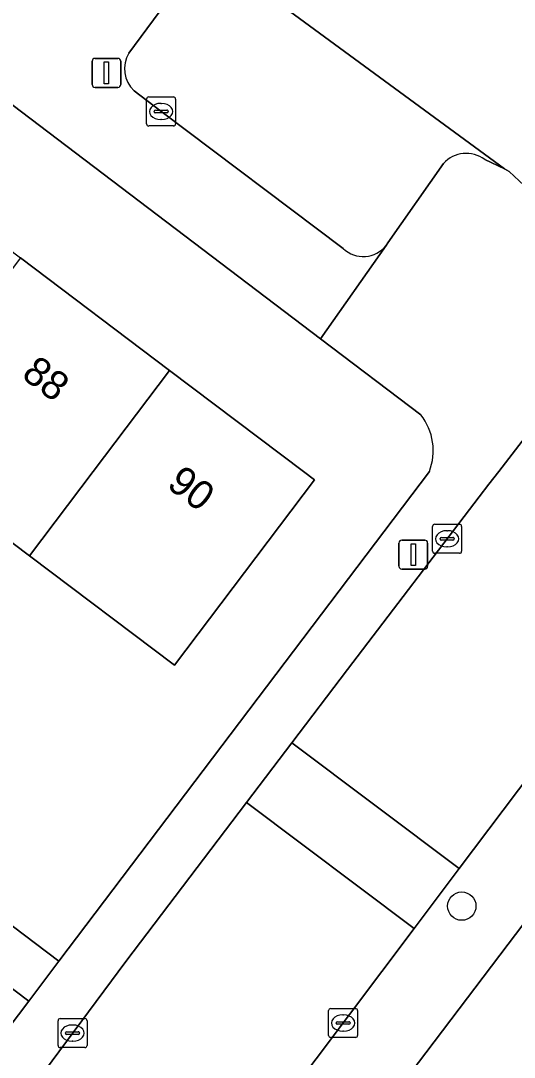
# Model space of a CAD drawing. Extents: x 159039 to 160102, y 381214 to 382524.
# Drawn here: x 159397.3 to 159414.31, y 381979.8 to 382015.54 of the extents above; entities that cross this region are included whole.
import ezdxf

# ---------------------------------------------------------------- set-up
doc = ezdxf.new("R2010")
doc.units = 0
for name, color, linetype in [('IMGEO_Boom', 7, 'Continuous'), ('IMGEO_Erf', 7, 'Continuous'), ('IMGEO_Kolk', 7, 'Continuous'), ('IMGEO_Lichtmast', 7, 'Continuous'), ('IMGEO_Pand', 7, 'Continuous'), ('IMGEO_Pand_nummerreeks', 7, 'Continuous'), ('IMGEO_Parkeervlak_open', 7, 'Continuous'), ('IMGEO_Rijbaan_lokaal_open', 7, 'Continuous'), ('IMGEO_Voetpad_open', 7, 'Continuous')]:
    doc.layers.add(name, color=color, linetype=linetype)

msp = doc.modelspace()

# ---------------------------------------------------------------- linework, layer by layer
at = {"layer": 'IMGEO_Boom'}
msp.add_circle((159412.501, 381985.013), 0.489, dxfattribs=at)
at = {"layer": 'IMGEO_Erf'}
for points in [[(159411.089, 382001.953), (159407.637, 382004.575), (159384.813, 382021.909), (159383.652, 382020.387), (159382.339, 382018.664), (159387.453, 382014.8), (159392.433, 382011.038), (159397.288, 382007.369), (159402.43, 382003.484), (159407.041, 382000), (159407.427, 381999.708), (159402.603, 381993.319), (159397.601, 381997.092), (159393.746, 382000), (159392.457, 382000.974), (159387.601, 382004.643)], [(159387.601, 382004.643), (159382.622, 382008.405), (159377.507, 382012.27), (159372.531, 382005.718), (159377.753, 382001.769), (159376.399, 381999.977), (159378.033, 381998.727), (159379.808, 382001.045), (159383.023, 381998.584), (159386.025, 381996.287), (159384.251, 381993.969), (159388.033, 381991.176), (159389.808, 381993.494), (159393.023, 381991.033), (159396.025, 381988.736), (159394.251, 381986.418), (159398.618, 381983.116), (159411.384, 382000)], [(159421.683, 381993.713), (159398.906, 381963.628), (159402.187, 381961.144), (159405.915, 381966.068), (159409.669, 381971.027), (159413.342, 381975.878), (159417.049, 381980.775), (159420.747, 381985.661), (159424.404, 381990.491), (159430.843, 381985.616), (159427.826, 381981.63), (159427.186, 381980.785), (159429.997, 381978.658), (159426.299, 381973.772), (159423.488, 381975.899), (159419.78, 381971.003), (159422.368, 381969.043), (159420.853, 381967.042), (159418.265, 381969.001), (159416.107, 381966.151), (159412.354, 381961.193), (159408.626, 381956.269), (159416.944, 381949.973)], [(159383.263, 381962.809), (159397.577, 381981.74), (159393.23, 381985.027)]]:
    msp.add_lwpolyline(points, dxfattribs=at)
msp.add_arc((159409.522, 382000.718), 1.996, 338.9276, 38.2515, dxfattribs=at)
at = {"layer": 'IMGEO_Kolk'}
for p, q in [((159401.638, 382011.988), (159401.638, 382012.84)), ((159401.713, 382012.914), (159402.565, 382012.914)), ((159402.126, 382012.694), (159402.151, 382012.694)), ((159402.639, 382012.84), (159402.639, 382011.988)), ((159401.897, 382012.408), (159401.897, 382012.42)), ((159402.335, 382012.371), (159401.937, 382012.371)), ((159401.94, 382012.457), (159402.338, 382012.457)), ((159402.381, 382012.42), (159402.381, 382012.408)), ((159402.565, 382011.914), (159401.713, 382011.914)), ((159402.149, 382012.134), (159402.124, 382012.134)), ((159411.495, 381997.253), (159411.495, 381998.105)), ((159411.57, 381998.179), (159412.422, 381998.179)), ((159411.983, 381997.959), (159412.008, 381997.959)), ((159412.496, 381998.105), (159412.496, 381997.253)), ((159411.754, 381997.673), (159411.754, 381997.685)), ((159412.192, 381997.636), (159411.794, 381997.636)), ((159411.797, 381997.722), (159412.195, 381997.722)), ((159412.238, 381997.685), (159412.238, 381997.673)), ((159412.006, 381997.399), (159411.981, 381997.399)), ((159412.422, 381997.179), (159411.57, 381997.179)), ((159407.911, 381980.557), (159407.911, 381981.409)), ((159407.986, 381981.483), (159408.838, 381981.483)), ((159408.399, 381981.263), (159408.424, 381981.263)), ((159408.912, 381981.409), (159408.912, 381980.557)), ((159398.585, 381980.208), (159398.585, 381981.06)), ((159398.66, 381981.134), (159399.512, 381981.134)), ((159399.073, 381980.914), (159399.098, 381980.914)), ((159399.586, 381981.06), (159399.586, 381980.208)), ((159408.17, 381980.977), (159408.17, 381980.989)), ((159408.608, 381980.94), (159408.21, 381980.94)), ((159408.213, 381981.026), (159408.611, 381981.026)), ((159408.654, 381980.989), (159408.654, 381980.977)), ((159398.844, 381980.628), (159398.844, 381980.64)), ((159399.282, 381980.591), (159398.884, 381980.591)), ((159398.887, 381980.677), (159399.285, 381980.677)), ((159399.328, 381980.64), (159399.328, 381980.628)), ((159408.838, 381980.483), (159407.986, 381980.483)), ((159408.422, 381980.703), (159408.397, 381980.703)), ((159399.512, 381980.134), (159398.66, 381980.134)), ((159399.096, 381980.354), (159399.071, 381980.354))]:
    msp.add_line(p, q, dxfattribs=at)
for points in [[(159401.638, 382011.988), (159401.638, 382012.84)], [(159401.713, 382012.914), (159402.565, 382012.914)], [(159402.639, 382012.84), (159402.639, 382011.988)], [(159402.565, 382011.914), (159401.713, 382011.914)], [(159411.495, 381997.253), (159411.495, 381998.105)], [(159411.57, 381998.179), (159412.422, 381998.179)], [(159412.496, 381998.105), (159412.496, 381997.253)], [(159412.422, 381997.179), (159411.57, 381997.179)], [(159407.911, 381980.557), (159407.911, 381981.409)], [(159407.986, 381981.483), (159408.838, 381981.483)], [(159408.912, 381981.409), (159408.912, 381980.557)], [(159398.585, 381980.208), (159398.585, 381981.06)], [(159398.66, 381981.134), (159399.512, 381981.134)], [(159399.586, 381981.06), (159399.586, 381980.208)], [(159408.838, 381980.483), (159407.986, 381980.483)], [(159399.512, 381980.134), (159398.66, 381980.134)]]:
    msp.add_lwpolyline(points, dxfattribs=at)
for centre, radius, start, end in [((159401.715, 382012.838), 0.0765, 91.552, 178.448), ((159401.715, 382012.838), 0.0765, 91.552, 178.448), ((159402.563, 382012.838), 0.0765, 1.552, 88.448), ((159402.563, 382012.838), 0.0765, 1.552, 88.448), ((159401.937, 382012.417), 0.0403, 85.8775, 175.7526), ((159401.934, 382012.407), 0.0366, 178.938, 274.7102), ((159402.338, 382012.414), 0.043, 264.8664, 352.4533), ((159402.342, 382012.419), 0.0386, 1.7309, 96.639), ((159401.715, 382011.99), 0.0765, 181.552, 268.448), ((159401.715, 382011.99), 0.0765, 181.552, 268.448), ((159402.563, 382011.99), 0.0765, 271.552, 358.448), ((159402.563, 382011.99), 0.0765, 271.552, 358.448), ((159411.572, 381998.103), 0.0765, 91.552, 178.448), ((159411.572, 381998.103), 0.0765, 91.552, 178.448), ((159412.42, 381998.103), 0.0765, 1.552, 88.448), ((159412.42, 381998.103), 0.0765, 1.552, 88.448), ((159411.794, 381997.682), 0.0403, 85.8775, 175.7526), ((159411.791, 381997.672), 0.0366, 178.938, 274.7102), ((159412.195, 381997.679), 0.043, 264.8664, 352.4533), ((159412.199, 381997.684), 0.0386, 1.7309, 96.639), ((159411.572, 381997.255), 0.0765, 181.552, 268.448), ((159411.572, 381997.255), 0.0765, 181.552, 268.448), ((159412.42, 381997.255), 0.0765, 271.552, 358.448), ((159412.42, 381997.255), 0.0765, 271.552, 358.448), ((159407.988, 381981.407), 0.0765, 91.552, 178.448), ((159407.988, 381981.407), 0.0765, 91.552, 178.448), ((159408.836, 381981.407), 0.0765, 1.552, 88.448), ((159408.836, 381981.407), 0.0765, 1.552, 88.448), ((159398.662, 381981.058), 0.0765, 91.552, 178.448), ((159398.662, 381981.058), 0.0765, 91.552, 178.448), ((159399.51, 381981.058), 0.0765, 1.552, 88.448), ((159399.51, 381981.058), 0.0765, 1.552, 88.448), ((159408.21, 381980.986), 0.0403, 85.8775, 175.7526), ((159408.207, 381980.976), 0.0366, 178.938, 274.7102), ((159408.611, 381980.983), 0.043, 264.8664, 352.4533), ((159408.615, 381980.988), 0.0386, 1.7309, 96.639), ((159398.884, 381980.637), 0.0403, 85.8775, 175.7526), ((159398.881, 381980.627), 0.0366, 178.938, 274.7102), ((159399.285, 381980.634), 0.043, 264.8664, 352.4533), ((159399.289, 381980.639), 0.0386, 1.7309, 96.639), ((159407.988, 381980.559), 0.0765, 181.552, 268.448), ((159407.988, 381980.559), 0.0765, 181.552, 268.448), ((159408.836, 381980.559), 0.0765, 271.552, 358.448), ((159408.836, 381980.559), 0.0765, 271.552, 358.448), ((159398.662, 381980.21), 0.0765, 181.552, 268.448), ((159398.662, 381980.21), 0.0765, 181.552, 268.448), ((159399.51, 381980.21), 0.0765, 271.552, 358.448), ((159399.51, 381980.21), 0.0765, 271.552, 358.448)]:
    msp.add_arc(centre, radius, start, end, dxfattribs=at)
for centre, major_axis, ratio, start_param, end_param in [((159402.125, 382012.414), (-0.387, 0.002), 0.722429, 4.712389, 7.853982), ((159402.15, 382012.414), (-0.39, 0.002), 0.717154, 1.570796, 4.712389), ((159411.982, 381997.679), (-0.387, 0.002), 0.722429, 4.712389, 7.853982), ((159412.007, 381997.679), (-0.39, 0.002), 0.717154, 1.570796, 4.712389), ((159408.398, 381980.983), (-0.387, 0.002), 0.722429, 4.712389, 7.853982), ((159408.423, 381980.983), (-0.39, 0.002), 0.717154, 1.570796, 4.712389), ((159399.072, 381980.634), (-0.387, 0.002), 0.722429, 4.712389, 7.853982), ((159399.097, 381980.634), (-0.39, 0.002), 0.717154, 1.570796, 4.712389)]:
    msp.add_ellipse(centre, major_axis=major_axis, ratio=ratio, start_param=start_param, end_param=end_param, dxfattribs=at)
at = {"layer": 'IMGEO_Lichtmast'}
for p, q in [((159399.761, 382013.346), (159399.761, 382014.146)), ((159399.761, 382014.146), (159399.761, 382013.346)), ((159399.861, 382014.246), (159400.651, 382014.246)), ((159400.651, 382014.246), (159399.861, 382014.246)), ((159400.751, 382014.146), (159400.751, 382013.346)), ((159400.751, 382013.346), (159400.751, 382014.146)), ((159400.651, 382013.246), (159399.861, 382013.246)), ((159399.861, 382013.246), (159400.651, 382013.246)), ((159410.433, 381997.634), (159411.223, 381997.634)), ((159411.223, 381997.634), (159410.433, 381997.634)), ((159410.333, 381996.734), (159410.333, 381997.534)), ((159410.333, 381997.534), (159410.333, 381996.734)), ((159411.323, 381997.534), (159411.323, 381996.734)), ((159411.323, 381996.734), (159411.323, 381997.534)), ((159411.223, 381996.634), (159410.433, 381996.634)), ((159410.433, 381996.634), (159411.223, 381996.634))]:
    msp.add_line(p, q, dxfattribs=at)
for points in [[(159400.181, 382014.121), (159400.331, 382014.121), (159400.331, 382013.371), (159400.181, 382013.371), (159400.181, 382014.121)], [(159410.753, 381997.509), (159410.903, 381997.509), (159410.903, 381996.759), (159410.753, 381996.759), (159410.753, 381997.509)]]:
    msp.add_lwpolyline(points, dxfattribs=at)
for centre, start, end in [((159399.861, 382014.146), 90, 180), ((159399.861, 382014.146), 90, 180), ((159400.651, 382014.146), 0, 90), ((159400.651, 382014.146), 360, 90), ((159399.861, 382013.346), 180, 270), ((159399.861, 382013.346), 180, 270), ((159400.651, 382013.346), 270, 0), ((159400.651, 382013.346), 270, 0), ((159410.433, 381997.534), 90, 180), ((159410.433, 381997.534), 90, 180), ((159411.223, 381997.534), 0, 90), ((159411.223, 381997.534), 360, 90), ((159410.433, 381996.734), 180, 270), ((159410.433, 381996.734), 180, 270), ((159411.223, 381996.734), 270, 0), ((159411.223, 381996.734), 270, 0)]:
    msp.add_arc(centre, 0.1, start, end, dxfattribs=at)
at = {"layer": 'IMGEO_Pand'}
for points in [[(159392.457, 382000.974), (159393.746, 382000), (159397.601, 381997.092), (159399.798, 382000), (159402.43, 382003.484), (159397.288, 382007.369)], [(159397.601, 381997.092), (159402.603, 381993.319), (159407.427, 381999.708), (159407.041, 382000), (159402.43, 382003.484), (159399.798, 382000)]]:
    msp.add_lwpolyline(points, close=True, dxfattribs=at)
at = {"layer": 'IMGEO_Parkeervlak_open'}
for points in [[(159413.29, 382010.753), (159413.97, 382010.442), (159403.117, 382018.417)], [(159402.922, 382017.001), (159401.024, 382014.421)], [(159401.208, 382013.131), (159402.125, 382012.426), (159408.415, 382007.686)], [(159409.892, 382007.795), (159409.957, 382007.888), (159411.869, 382010.619)]]:
    msp.add_lwpolyline(points, dxfattribs=at)
for centre, radius, start, end in [((159401.905, 382013.889), 1.03, 148.862, 227.3733), ((159412.653, 382009.91), 1.057, 52.9226, 137.8515), ((159409.104, 382008.416), 1.004, 226.6775, 321.7639)]:
    msp.add_arc(centre, radius, start, end, dxfattribs=at)
at = {"layer": 'IMGEO_Rijbaan_lokaal_open'}
for points in [[(159403.117, 382018.417), (159413.97, 382010.442), (159414.131, 382010.342), (159414.649, 382009.857), (159428.781, 381998.963), (159429.268, 381998.566), (159433.841, 381994.834), (159441.923, 381988.326)], [(159416.185, 382003.138), (159413.774, 382000), (159413.438, 381999.563), (159413.105, 381999.127), (159408.558, 381993.176), (159406.641, 381990.648), (159412.416, 381986.311), (159415.967, 381991.036), (159421.514, 381998.432)]]:
    msp.add_lwpolyline(points, dxfattribs=at)
for points in [[(159410.86, 381984.24), (159412.416, 381986.311), (159406.641, 381990.648), (159405.076, 381988.584)], [(159410.86, 381984.24), (159405.076, 381988.584), (159400.92, 381983.103), (159395.307, 381975.538), (159387.743, 381965.439), (159383.665, 381960.085), (159381.096, 381956.711), (159376.604, 381950.827), (159371.448, 381943.987), (159367.623, 381938.959), (159365.26, 381935.852), (159364.911, 381935.394), (159361.248, 381930.665), (159358.041, 381926.414), (159363.697, 381922.105), (159365.099, 381923.996), (159369.627, 381929.935), (159375.274, 381937.448), (159382.82, 381947.331), (159392.08, 381959.597), (159405.257, 381976.785)]]:
    msp.add_lwpolyline(points, close=True, dxfattribs=at)
at = {"layer": 'IMGEO_Voetpad_open'}
for points in [[(159387.584, 382023.308), (159386.738, 382024.067), (159386.549, 382024.218), (159385.197, 382022.419), (159384.813, 382021.909), (159407.637, 382004.575), (159409.892, 382007.795)], [(159401.024, 382014.421), (159402.922, 382017.001)], [(159408.415, 382007.686), (159402.125, 382012.426), (159401.208, 382013.131)], [(159411.869, 382010.619), (159409.957, 382007.888), (159409.892, 382007.795), (159407.637, 382004.575), (159411.089, 382001.953)], [(159415.443, 382009.112), (159414.649, 382009.857), (159414.131, 382010.342), (159413.97, 382010.442), (159413.29, 382010.753)], [(159364.911, 381935.394), (159365.26, 381935.852), (159364.864, 381936.156), (159367.227, 381939.263), (159367.623, 381938.959), (159371.448, 381943.987), (159376.604, 381950.827), (159381.096, 381956.711), (159383.665, 381960.085), (159387.743, 381965.439), (159395.307, 381975.538), (159400.92, 381983.103), (159405.076, 381988.584), (159406.641, 381990.648), (159408.558, 381993.176), (159413.105, 381999.127), (159413.438, 381999.563), (159413.774, 382000), (159416.185, 382003.138)], [(159411.384, 382000), (159398.618, 381983.116), (159397.577, 381981.74), (159383.263, 381962.809), (159381.764, 381960.886), (159379.871, 381958.305), (159379.509, 381957.83), (159378.352, 381956.413), (159364.085, 381937.613), (159363.026, 381936.217), (159362.932, 381936.091), (159349.407, 381917.941), (159348.619, 381918.534), (159345.009, 381914.041)], [(159421.514, 381998.432), (159415.967, 381991.036), (159412.416, 381986.311), (159410.86, 381984.24), (159405.257, 381976.785), (159392.08, 381959.597), (159382.82, 381947.331), (159375.274, 381937.448), (159369.627, 381929.935), (159365.099, 381923.996), (159363.697, 381922.105), (159362.178, 381920.056), (159360.046, 381917.18), (159356.505, 381912.787)], [(159358.765, 381910.606), (159381.864, 381941.117), (159382.726, 381942.256), (159397.868, 381962.257), (159398.906, 381963.628), (159421.683, 381993.713)]]:
    msp.add_lwpolyline(points, dxfattribs=at)
msp.add_lwpolyline([(159384.251, 381993.969), (159381.263, 381996.255), (159378.033, 381998.727), (159376.399, 381999.977), (159376.296, 381999.841), (159374.226, 382001.407), (159373.865, 382000.929), (159373.335, 382000.228), (159377.144, 381997.313), (159380.28, 381994.913), (159383.352, 381992.563), (159387.022, 381989.777), (159390.158, 381987.377), (159393.23, 381985.027), (159397.577, 381981.74), (159398.618, 381983.116), (159394.251, 381986.418), (159391.264, 381988.704), (159388.033, 381991.176)], close=True, dxfattribs=at)
for centre, radius, start, end in [((159401.905, 382013.889), 1.03, 148.862, 227.3733), ((159412.653, 382009.91), 1.057, 52.9226, 137.8515), ((159409.104, 382008.416), 1.004, 226.6775, 321.7639), ((159409.522, 382000.718), 1.996, 338.9276, 38.2515)]:
    msp.add_arc(centre, radius, start, end, dxfattribs=at)

# ---------------------------------------------------------------- texts
at = {"layer": 'IMGEO_Pand_nummerreeks'}
for s, rotation, p in [('88', 322.9265, (159397.285, 382003.26)), ('90', 322.924, (159402.294, 381999.475))]:
    msp.add_text(s, height=1, rotation=rotation, dxfattribs=at).set_placement(p)

doc.saveas('drawing.dxf')
